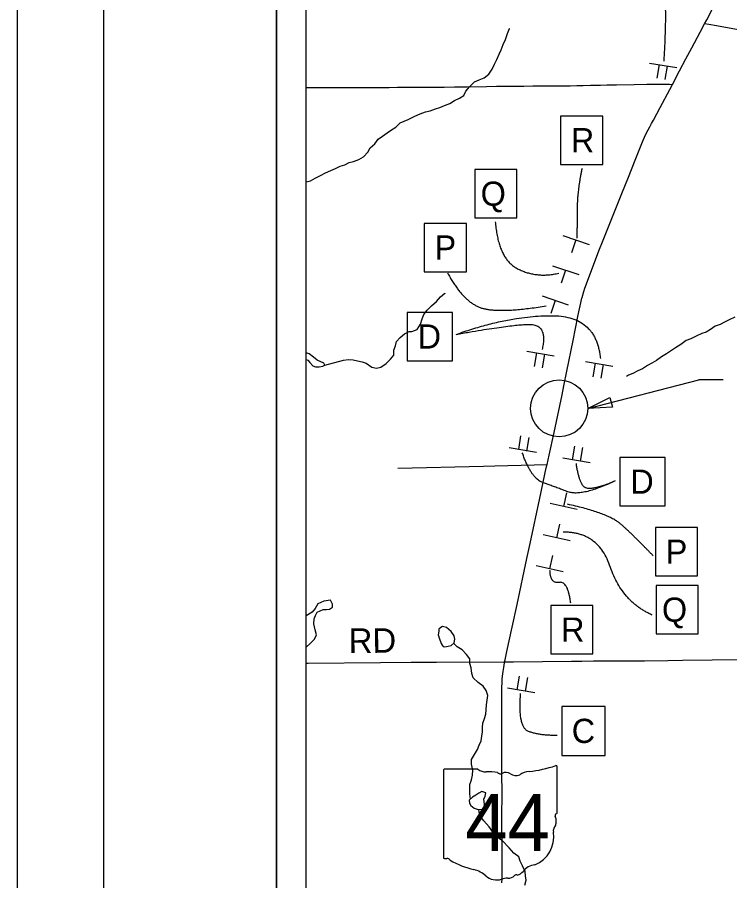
# Model space of a CAD drawing. Extents: x 0 to 34, y 0 to 22.
# Drawn here: x 0 to 4.121, y 9.413 to 14.409 of the extents above; entities that cross this region are included whole.
import ezdxf

# ---------------------------------------------------------------- set-up
doc = ezdxf.new("R2010")
doc.units = 0
for name, color, linetype in [('GM_X_County_Road', 7, 'Continuous'), ('GM_X_County_Road_Text', 7, 'Continuous'), ('GM_X_Minor_Lake', 7, 'Continuous'), ('GM_X_Minor_River', 7, 'Continuous'), ('GM_X_State_Location', 7, 'Continuous'), ('GM_X_State_Route', 7, 'Continuous'), ('GM_X_State_Shield', 7, 'Continuous'), ('GM_X_Township_Road', 7, 'Continuous'), ('SH_Border', 7, 'Continuous'), ('SH_Cut_Line', 7, 'Continuous'), ('SH_Text', 7, 'Continuous'), ('SN_P_Signs', 7, 'Continuous')]:
    doc.layers.add(name, color=color, linetype=linetype)

msp = doc.modelspace()

# ---------------------------------------------------------------- linework, layer by layer
at = {"layer": 'GM_X_County_Road'}
for points in [[(1.6712, 14.0027), (1.72, 14.0029), (1.7977, 14.0026), (1.8737, 14.0031), (1.9047, 14.0028), (1.9745, 14.0028), (2.0646, 14.0034), (2.15, 14.0036), (2.1998, 14.0042), (2.2587, 14.0044), (2.355, 14.0043), (2.4016, 14.0042), (2.4684, 14.0049), (2.529, 14.0058), (2.6005, 14.0069), (2.7139, 14.0086), (2.7714, 14.0096), (2.8133, 14.0106), (2.8317, 14.0111), (2.8606, 14.0114), (2.8851, 14.0114), (2.8989, 14.0113), (2.9299, 14.0112), (2.9827, 14.0119), (3.0121, 14.0122), (3.0787, 14.0118), (3.1484, 14.0123), (3.1981, 14.0132), (3.2369, 14.0138), (3.2727, 14.0145), (3.3145, 14.0155), (3.3392, 14.0162), (3.3732, 14.0169), (3.4102, 14.0173), (3.4667, 14.0184), (3.5689, 14.0206), (3.6406, 14.0228), (3.6986, 14.0226), (3.7484, 14.0227), (3.7717, 14.0216), (3.789, 14.0207)], [(2.8188, 10.6798), (2.8697, 10.68), (3.2053, 10.6832), (3.2658, 10.6842), (3.3326, 10.6853), (3.5691, 10.6851), (3.6275, 10.6855), (3.7629, 10.6872), (3.8468, 10.6884), (4.0192, 10.6911), (4.246, 10.6928), (4.4341, 10.6952), (4.5506, 10.6961), (4.6827, 10.6977), (4.8396, 10.6995), (4.9411, 10.701)], [(1.6712, 10.6714), (1.6828, 10.6715), (2.1007, 10.6753), (2.2778, 10.6771), (2.4239, 10.6784), (2.8188, 10.6798)]]:
    msp.add_lwpolyline(points, dxfattribs=at)
at = {"layer": 'GM_X_Minor_Lake'}
for p, q in [((1.6712, 12.4286), (1.6811, 12.4243)), ((2.44, 10.8193), (2.4525, 10.7862)), ((2.652, 9.9086), (2.6331, 9.897))]:
    msp.add_line(p, q, dxfattribs=at)
for points in [[(1.6811, 12.4243), (1.6916, 12.4111), (1.7088, 12.3932), (1.724, 12.3858), (1.7457, 12.3869), (1.7675, 12.3908), (1.7788, 12.3957), (1.774, 12.407), (1.735, 12.4257), (1.7131, 12.4416), (1.6874, 12.4623), (1.6712, 12.4668)], [(1.6712, 10.764), (1.6938, 10.785), (1.7182, 10.8099), (1.7313, 10.8356), (1.7225, 10.8658), (1.7147, 10.899), (1.7173, 10.9293), (1.7256, 10.9484), (1.735, 10.9674), (1.7689, 10.9819), (1.7888, 10.982), (1.8067, 10.984), (1.8227, 10.9965), (1.8226, 11.0136), (1.812, 11.0372)], [(1.812, 11.0372), (1.7733, 11.0302), (1.7393, 11.0158), (1.7234, 10.9882), (1.7056, 10.9672), (1.6712, 10.9461)], [(1.6712, 10.764), (1.6938, 10.785), (1.7182, 10.8099), (1.7313, 10.8356), (1.7225, 10.8658), (1.7147, 10.899), (1.7173, 10.9293), (1.7256, 10.9484), (1.735, 10.9674), (1.7689, 10.9819), (1.7888, 10.982), (1.8067, 10.984), (1.8227, 10.9965), (1.8226, 11.0136), (1.812, 11.0372), (1.7733, 11.0302), (1.7393, 11.0158), (1.7234, 10.9882), (1.7056, 10.9672), (1.6712, 10.9461)], [(2.4525, 10.7862), (2.4566, 10.7768), (2.4642, 10.7693), (2.4728, 10.7665), (2.4926, 10.7705), (2.5097, 10.7736), (2.5275, 10.789), (2.531, 10.8109), (2.527, 10.8298), (2.5087, 10.8552), (2.482, 10.8786), (2.4592, 10.885), (2.4488, 10.8792), (2.4385, 10.8686), (2.4377, 10.8563), (2.4351, 10.8363), (2.44, 10.8193)], [(2.6331, 9.897), (2.6144, 9.8788), (2.6146, 9.8617), (2.6233, 9.8476), (2.6433, 9.8326), (2.6652, 9.8262), (2.6889, 9.8274), (2.701, 9.839), (2.7027, 9.8561), (2.6986, 9.8855), (2.706, 9.9026), (2.7105, 9.9226), (2.6877, 9.9299), (2.6698, 9.9193), (2.652, 9.9086)]]:
    msp.add_lwpolyline(points, dxfattribs=at)
at = {"layer": 'GM_X_Minor_River'}
for points in [[(2.2607, 13.8171), (2.2993, 13.8375), (2.3295, 13.8511), (2.3616, 13.862), (2.388, 13.868), (2.4191, 13.8797), (2.4446, 13.8876), (2.471, 13.8984), (2.5021, 13.9111), (2.5284, 13.9285), (2.5576, 13.9402), (2.583, 13.9566), (2.595, 13.9824), (2.6146, 14.0073), (2.6437, 14.0352), (2.671, 14.0469), (2.7002, 14.0596), (2.7265, 14.0808), (2.747, 14.1095), (2.76, 14.1372), (2.7729, 14.1639), (2.7877, 14.1964), (2.7988, 14.2212), (2.8108, 14.2517), (2.8237, 14.2813), (2.8347, 14.3156), (2.8476, 14.3433), (2.8495, 14.3443)], [(1.6712, 13.4567), (1.6958, 13.4637), (1.7222, 13.479), (1.7533, 13.4935), (1.7835, 13.5089), (1.8127, 13.5234), (1.84, 13.534), (1.8674, 13.5484), (1.8948, 13.5562), (1.9202, 13.5687), (1.9448, 13.5756), (1.9749, 13.5862), (2.0023, 13.6026), (2.0276, 13.6293), (2.0416, 13.6531), (2.0689, 13.677), (2.0876, 13.7037), (2.113, 13.721), (2.1394, 13.7401), (2.1648, 13.7584), (2.1892, 13.7737), (2.2146, 13.7986), (2.2607, 13.8171)], [(2.2821, 12.5919), (2.3121, 12.6025), (2.3317, 12.6341), (2.3427, 12.6646), (2.3509, 12.6893), (2.3705, 12.7143), (2.3949, 12.7392), (2.4249, 12.7652), (2.4483, 12.7921), (2.4726, 12.8132), (2.4727, 12.8113)], [(4.1501, 12.6733), (4.1181, 12.6587), (4.0898, 12.6451), (4.0654, 12.6325), (4.0371, 12.6217), (4.0089, 12.6033), (3.9835, 12.5878), (3.959, 12.5799), (3.926, 12.5634), (3.8959, 12.5488), (3.8685, 12.5381), (3.8375, 12.5159), (3.8074, 12.4965), (3.783, 12.4811), (3.7558, 12.4618), (3.7266, 12.4453), (3.6975, 12.4241), (3.6711, 12.4076), (3.6457, 12.395), (3.6166, 12.3747), (3.5883, 12.3639), (3.561, 12.3475), (3.5346, 12.3386), (3.5243, 12.3309)], [(1.7788, 12.3957), (1.8874, 12.4249), (1.9148, 12.4289), (1.9422, 12.4263), (1.9678, 12.4208), (1.9944, 12.4163), (2.0181, 12.4079), (2.0504, 12.3854), (2.077, 12.379), (2.1025, 12.3848), (2.1335, 12.405), (2.1589, 12.4308), (2.1776, 12.4546), (2.1774, 12.4821), (2.1876, 12.5078), (2.1941, 12.5325), (2.2147, 12.5564), (2.2391, 12.5784), (2.2665, 12.5919), (2.2821, 12.5919)], [(2.6207, 9.8849), (2.6168, 9.9158), (2.6172, 9.9699), (2.6263, 9.9966), (2.6336, 10.0242), (2.6342, 10.0527), (2.6263, 10.0868), (2.6269, 10.1143), (2.6446, 10.1439), (2.6622, 10.1717), (2.6714, 10.1984), (2.6825, 10.2232), (2.6869, 10.2488), (2.6914, 10.2755), (2.6902, 10.2992), (2.6927, 10.3248), (2.7019, 10.3525), (2.7101, 10.3763), (2.7127, 10.402), (2.7142, 10.4305), (2.7177, 10.4571), (2.7222, 10.4847), (2.7114, 10.514), (2.6941, 10.5384), (2.6654, 10.5599), (2.6377, 10.5871), (2.6298, 10.6117), (2.6257, 10.6449), (2.6178, 10.6704), (2.6184, 10.698), (2.5973, 10.7224), (2.5724, 10.7496), (2.5438, 10.7673), (2.5244, 10.7863)], [(2.9362, 9.3871), (2.9435, 9.4166), (2.9404, 9.4413), (2.9382, 9.4659), (2.9226, 9.4999), (2.9081, 9.5263), (2.9003, 9.5509), (2.8716, 9.5724), (2.8457, 9.6043), (2.8045, 9.6466), (2.7778, 9.6624), (2.7519, 9.6925), (2.7298, 9.7254), (2.6981, 9.7602), (2.6789, 9.7846), (2.672, 9.8092), (2.67, 9.8265)]]:
    msp.add_lwpolyline(points, dxfattribs=at)
at = {"layer": 'GM_X_State_Route'}
for points in [[(2.8188, 10.6798), (2.8211, 10.6905), (2.8309, 10.7394), (2.862, 10.8802), (2.8908, 11.0123), (2.9468, 11.2768), (2.9662, 11.3648), (3.0221, 11.6262), (3.0598, 11.8025), (3.0641, 11.8208), (3.0763, 11.8753), (3.105, 12.0075), (3.151, 12.2249), (3.1616, 12.2766), (3.1788, 12.3619), (3.2143, 12.5386), (3.2421, 12.6785), (3.2656, 12.7835), (3.2665, 12.7872), (3.2767, 12.8231), (3.2823, 12.841), (3.2918, 12.8673), (3.3578, 13.0433), (3.3675, 13.0679), (3.3842, 13.1097), (3.4959, 13.3898), (3.5343, 13.4846), (3.574, 13.5825), (3.5999, 13.649), (3.6158, 13.6877), (3.6278, 13.7163), (3.6335, 13.7291), (3.6484, 13.7582), (3.6581, 13.7759), (3.6687, 13.7949), (3.6789, 13.814), (3.7178, 13.8865), (3.7739, 13.9921), (3.789, 14.0207), (3.8304, 14.0994), (3.867, 14.1679), (3.9015, 14.2322), (3.9492, 14.3229), (3.9756, 14.3721), (3.9874, 14.394), (4.0249, 14.4655)], [(2.8034, 9.4007), (2.8036, 9.4256), (2.804, 9.5885), (2.8035, 9.7514), (2.8036, 9.9493), (2.8035, 10.004), (2.8034, 10.0263), (2.8034, 10.0433), (2.8031, 10.1064), (2.8027, 10.1823), (2.8022, 10.5025), (2.8023, 10.5153), (2.8024, 10.522), (2.8028, 10.5326), (2.8041, 10.5582), (2.8047, 10.5705), (2.8052, 10.579), (2.8067, 10.5974), (2.8099, 10.6239), (2.8134, 10.6473), (2.8177, 10.6732), (2.8188, 10.6798)]]:
    msp.add_lwpolyline(points, dxfattribs=at)
at = {"layer": 'GM_X_State_Shield'}
for p, q in [((2.4643, 10.0498), (2.4643, 9.5495)), ((2.6638, 10.0585), (2.4708, 10.0585)), ((3.1234, 9.8091), (3.1234, 10.0709)), ((3.1234, 9.8092), (3.1234, 9.8091))]:
    msp.add_line(p, q, dxfattribs=at)
for centre, radius, start, end in [((2.4718, 10.0509), 0.00764, 98.1301, 188.1301), ((2.7098, 10.1165), 0.0741, 231.6195, 271.1119), ((2.7343, 9.7776), 0.2659, 80.4867, 94.9883), ((2.9778, 9.9056), 0.1406, 97.3462, 120.7689), ((2.8886, 10.7405), 0.699, 275.8445, 288.9065), ((3.1161, 10.0719), 0.00734, 351.8621, 97.738), ((2.7947, 10.0535), 0.0214, 219.7921, 297.1024), ((2.8261, 9.9957), 0.0444, 54.4667, 119.1411), ((2.8834, 10.075), 0.0534, 233.8562, 294.8282), ((3.1217, 9.7899), 0.0114, 107.944, 210.337), ((3.1156, 9.8081), 0.00785, 289.6038, 7.7341), ((3.0495, 9.7568), 0.0682, 340.033, 23.6496), ((2.9278, 9.6663), 0.1748, 292.3089, 8.9858), ((3.1497, 9.6996), 0.0496, 136.8065, 186.9296), ((2.4719, 9.5484), 0.0077, 171.9584, 258.3066), ((2.4731, 9.5996), 0.0588, 267.339, 280.6039), ((2.4851, 9.5207), 0.0212, 29.7484, 93.2717), ((2.7527, 9.9702), 0.5048, 240.4129, 257.1985), ((3.0015, 9.4091), 0.0958, 94.4031, 142.5768), ((2.6022, 9.3248), 0.1579, 47.1842, 75.836), ((2.8383, 9.4807), 0.0534, 268.777, 315.5493), ((2.8866, 9.4323), 0.015, 65.7517, 132.6484), ((2.8802, 9.5011), 0.0565, 282.8732, 323.2771), ((2.7731, 9.5182), 0.1002, 230.7004, 286.2918), ((2.831, 9.3452), 0.0824, 85.6951, 111.2099)]:
    msp.add_arc(centre, radius, start, end, dxfattribs=at)
at = {"layer": 'GM_X_Township_Road'}
for points in [[(4.9984, 14.0529), (4.9978, 14.0681), (4.9972, 14.096), (4.9973, 14.1039), (4.9967, 14.1291), (4.9949, 14.137), (4.9923, 14.1462), (4.9858, 14.1573), (4.9829, 14.1611), (4.9746, 14.1688), (4.9681, 14.1733), (4.9567, 14.1791), (4.9417, 14.1842), (4.9204, 14.1894), (4.8108, 14.2123), (4.6753, 14.24), (4.5821, 14.2577), (4.4938, 14.2755), (4.3625, 14.3005), (4.2433, 14.3223), (4.1593, 14.338), (4.0449, 14.3593), (3.9991, 14.3678), (3.9756, 14.3721)], [(2.2016, 11.7997), (2.696, 11.8119), (2.7628, 11.8139), (2.9898, 11.82), (3.0641, 11.8208)]]:
    msp.add_lwpolyline(points, dxfattribs=at)
at = {"layer": 'SH_Border'}
for points in [[(0.5, 21.5), (1.5, 21.5), (1.5, 0.5), (0.5, 0.5)], [(1.5, 21.5), (33.5, 21.5), (33.5, 0.5), (1.5, 0.5)]]:
    msp.add_lwpolyline(points, close=True, dxfattribs=at)
at = {"layer": 'SH_Cut_Line'}
msp.add_lwpolyline([(0, 0), (34, 0), (34, 22), (0, 22)], close=True, dxfattribs=at)
at = {"layer": 'SH_Text'}
for p in [(3.2994, 12.1463), (4.0824, 12.3117)]:
    msp.add_line(p, (3.9424, 12.3117), dxfattribs=at)
for points in [[(1.6712, 21.2991), (18.6712, 21.2991), (18.6712, 4.2991), (1.6712, 4.2991)], [(3.1423, 13.558), (3.3864, 13.558), (3.3864, 13.8373), (3.1423, 13.8373)], [(2.6458, 13.2484), (2.8899, 13.2484), (2.8899, 13.5278), (2.6458, 13.5278)], [(2.3539, 12.937), (2.5981, 12.937), (2.5981, 13.2164), (2.3539, 13.2164)], [(2.2552, 12.4222), (2.5171, 12.4222), (2.5171, 12.7015), (2.2552, 12.7015)], [(3.442, 12.154), (3.2994, 12.1463), (3.428, 12.2083)], [(3.485, 11.5824), (3.747, 11.5824), (3.747, 11.8617), (3.485, 11.8617)], [(3.691, 11.1771), (3.9351, 11.1771), (3.9351, 11.4564), (3.691, 11.4564)], [(3.6943, 10.8416), (3.9384, 10.8416), (3.9384, 11.1209), (3.6943, 11.1209)], [(3.0857, 10.7261), (3.3298, 10.7261), (3.3298, 11.0054), (3.0857, 11.0054)], [(3.1492, 10.1385), (3.4001, 10.1385), (3.4001, 10.4213), (3.1492, 10.4213)]]:
    msp.add_lwpolyline(points, close=True, dxfattribs=at)
msp.add_circle((3.1344, 12.1463), 0.1651, dxfattribs=at)
for points in [[(3.4273, 14.6286), (3.526, 14.6286), (3.7233, 14.6286), (3.7574, 14.4615), (3.7391, 14.1553)], [(3.2664, 13.5347), (3.239, 13.4051), (3.239, 13.2324), (3.2357, 13.1317)], [(2.7646, 13.2264), (2.7815, 13.0138), (3.0006, 12.8976), (3.1315, 12.9284)], [(2.4883, 12.9299), (2.5862, 12.7518), (2.8024, 12.6968), (3.0595, 12.7397)], [(2.5386, 12.5742), (2.844, 12.6843), (3.3489, 12.6805), (3.3725, 12.4351)], [(2.5386, 12.5742), (2.863, 12.6331), (3.0689, 12.6304), (3.0353, 12.4861)], [(3.4583, 11.7263), (3.2633, 11.634), (3.1051, 11.6932), (2.973, 11.7403), (2.9208, 11.8896)], [(3.4583, 11.7263), (3.3022, 11.6591), (3.2459, 11.7328), (3.2336, 11.8265)], [(3.6783, 11.2929), (3.5698, 11.4057), (3.4202, 11.5402), (3.1828, 11.5912)], [(3.6729, 10.9499), (3.4962, 11.0297), (3.3618, 11.4322), (3.158, 11.43)], [(3.2013, 11.0182), (3.185, 11.1489), (3.0836, 11.1293), (3.0811, 11.208)], [(3.1217, 10.2535), (3.0098, 10.2535), (2.896, 10.3047), (2.911, 10.4964)]]:
    msp.add_open_spline(points, degree=2, dxfattribs=at)
at = {"layer": 'SN_P_Signs'}
for p, q in [((3.657, 14.1445), (3.8147, 14.1177)), ((3.7122, 14.1351), (3.6988, 14.0562)), ((3.7358, 14.1311), (3.7358, 14.1311)), ((3.7358, 14.1311), (3.7358, 14.1311)), ((3.7595, 14.1271), (3.7461, 14.0482)), ((3.1557, 13.147), (3.3071, 13.0951)), ((3.2314, 13.121), (3.2055, 13.0454)), ((3.0957, 12.9718), (3.2471, 12.9199)), ((3.1714, 12.9459), (3.1455, 12.8702)), ((3.0357, 12.7966), (3.1871, 12.7447)), ((3.1114, 12.7707), (3.0855, 12.695)), ((2.9473, 12.4768), (3.1051, 12.4499)), ((3.0026, 12.4674), (2.9891, 12.3885)), ((3.0262, 12.4633), (3.0262, 12.4633)), ((3.0262, 12.4633), (3.0262, 12.4633)), ((3.0499, 12.4593), (3.0365, 12.3805)), ((3.2869, 12.4179), (3.4447, 12.3911)), ((3.3421, 12.4085), (3.3287, 12.3296)), ((3.3658, 12.4045), (3.3658, 12.4045)), ((3.3658, 12.4045), (3.3658, 12.4045)), ((3.3895, 12.4005), (3.376, 12.3216)), ((2.9, 11.9076), (2.9134, 11.9864)), ((2.9473, 11.8995), (2.9607, 11.9784)), ((3.0025, 11.8901), (2.8447, 11.917)), ((2.9236, 11.9035), (2.9236, 11.9035)), ((2.9236, 11.9035), (2.9236, 11.9035)), ((3.2111, 11.8487), (3.2245, 11.9276)), ((3.2584, 11.8407), (3.2718, 11.9195)), ((3.3136, 11.8313), (3.1559, 11.8581)), ((3.2347, 11.8447), (3.2347, 11.8447)), ((3.2347, 11.8447), (3.2347, 11.8447)), ((3.1604, 11.5786), (3.1778, 11.6566)), ((3.2384, 11.5611), (3.0823, 11.596)), ((3.12, 11.3978), (3.1374, 11.4759)), ((3.1981, 11.3804), (3.0419, 11.4152)), ((3.0797, 11.2171), (3.0971, 11.2952)), ((3.1577, 11.1996), (3.0016, 11.2345)), ((2.8913, 10.5182), (2.9047, 10.5971)), ((2.9387, 10.5102), (2.9521, 10.589)), ((2.9939, 10.5008), (2.8361, 10.5276)), ((2.915, 10.5142), (2.915, 10.5142)), ((2.915, 10.5142), (2.915, 10.5142))]:
    msp.add_line(p, q, dxfattribs=at)

# ---------------------------------------------------------------- texts
at = {"layer": 'GM_X_County_Road_Text'}
msp.add_text('RD', height=0.14205, rotation=0.4827, dxfattribs=at).set_placement((1.9175, 10.7304))
at = {"layer": 'GM_X_State_Location'}
msp.add_text('44', height=0.000473, rotation=0, dxfattribs=at).set_placement((2.7609, 10.9524))
for s, p in [('s', (2.8802, 10.9868)), ('r', (2.8801, 10.9868))]:
    msp.add_text(s, height=0.000473, dxfattribs=at).set_placement(p)
at = {"layer": 'GM_X_State_Shield'}
msp.add_text('44', height=0.32959, dxfattribs=at).set_placement((2.5907, 9.5848))
at = {"layer": 'SH_Text'}
for s, p in [('R', (3.202, 13.628)), ('Q', (2.6802, 13.3184)), ('P', (2.4134, 13.007)), ('D', (2.3157, 12.4922)), ('D', (3.5456, 11.6524)), ('P', (3.7505, 11.2471)), ('Q', (3.7287, 10.9116)), ('R', (3.1455, 10.7961)), ('C', (3.2068, 10.2102))]:
    msp.add_text(s, height=0.14, dxfattribs=at).set_placement(p)

doc.saveas('drawing.dxf')
